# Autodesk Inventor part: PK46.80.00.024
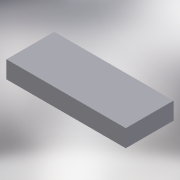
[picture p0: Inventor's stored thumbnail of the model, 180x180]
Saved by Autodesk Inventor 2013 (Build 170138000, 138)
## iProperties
Created: 2005-05
Part Number: PK46.80.00.024
Material: Steel, Mild
Document SubType Name: Modeling
Designer: salex
Manufacturer: Standard
Standards Organization: Custom
Density: 7.86 g/cm^3
Mass: 608.678 g
Surface Area: 146.08 cm^2
Volume: 77.44 cm^3
Author: salex
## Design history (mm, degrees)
sketch "Эскиз1"
  geometry: L1 (0, 0)-(110, 0); L2 (110, 0)-(110, 44); L3 (110, 44)-(0, 44); L4 (0, 44)-(0, 0)
  constraints: 8 end point, 2 parallel, 1 horizontal, 1 perpendicular, 1 other
  dimensions: "d0" = 110 distance of L1.start L1.end; "d1" = 44 distance of L3.end L1.start
extrude "Выдавливание1" new body sketch "Эскиз1" distance "d2" = 16; taper "d3" = 0 deg
body "Solid1"
